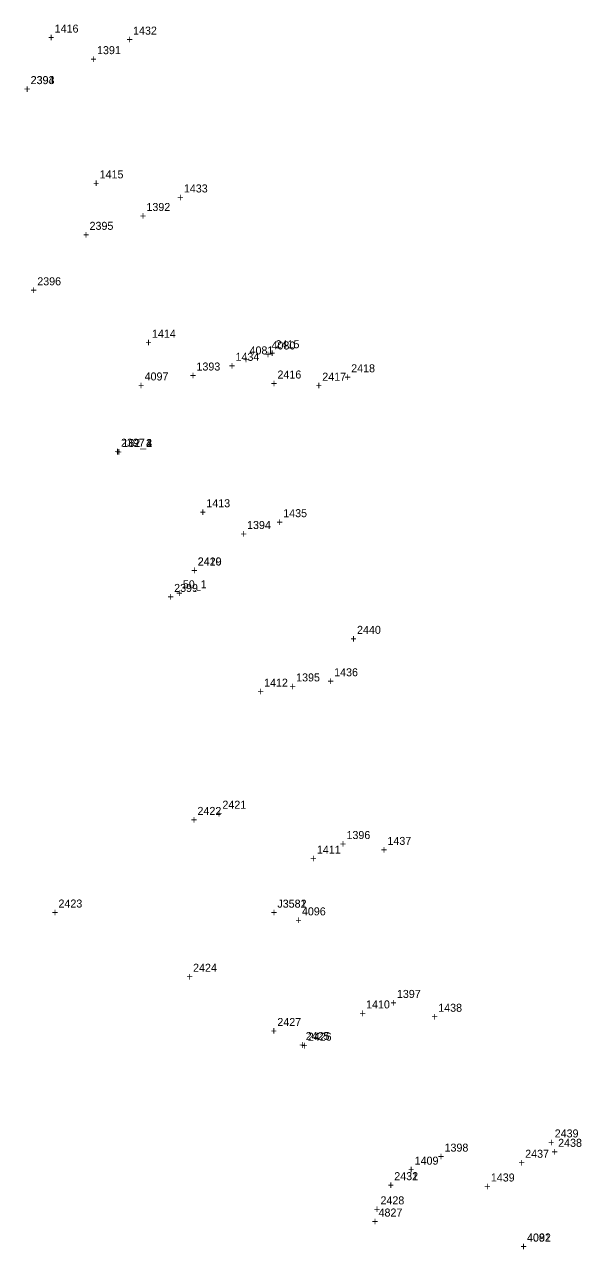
# Model space of a CAD drawing. Extents: x 1036751 to 1042192, y 772604 to 785439.
# Drawn here: x 1038206.7 to 1038380.7, y 779383.2 to 779766 of the extents above; entities that cross this region are included whole.
import ezdxf

# ---------------------------------------------------------------- set-up
doc = ezdxf.new("R2010")
doc.units = 0
for name, color, linetype in [('S_Control_Geodetic_ControlPoint', 7, 'Continuous'), ('S_Control_Temp_Traverse', 7, 'Continuous'), ('S_Drainage_CB', 7, 'Continuous'), ('S_Drainage_Sump', 7, 'Continuous'), ('S_Ground_Elevation', 7, 'Continuous'), ('S_Property_IronPipeFound', 7, 'Continuous'), ('S_Property_Mailbox', 7, 'Continuous'), ('S_Roadway_Centerline', 7, 'Continuous'), ('S_Roadway_Edge_Pavement', 7, 'Continuous'), ('S_Traffic_Sign_DoublePost', 7, 'Continuous'), ('S_Traffic_Sign_SinglePost', 7, 'Continuous'), ('S_Trees_Conifer_Pay', 7, 'Continuous'), ('S_Utilities_GuyWire3', 7, 'Continuous'), ('S_Utilities_Hydrant', 7, 'Continuous'), ('S_Utilities_Pole_Power', 7, 'Continuous'), ('S_Utilities_UG_Electrical_Line', 7, 'Continuous'), ('S_Utilities_UG_Water_Line', 7, 'Continuous')]:
    doc.layers.add(name, color=color, linetype=linetype)

msp = doc.modelspace()

# ---------------------------------------------------------------- texts
at = {"layer": 'S_Control_Geodetic_ControlPoint'}
for s, p in [('+', (1038254.14, 779587.08)), ('+', (1038254.14, 779587.08)), ('+', (1038254.14, 779587.08)), ('+', (1038254.14, 779587.08)), ('+', (1038254.14, 779587.08)), ('+', (1038254.14, 779587.08)), ('+', (1038254.14, 779587.08)), ('+', (1038254.14, 779587.08)), ('+', (1038254.14, 779587.08)), ('+', (1038254.14, 779587.08)), ('+', (1038254.14, 779587.08)), ('+', (1038254.14, 779587.08)), ('+', (1038254.14, 779587.08)), ('+', (1038254.14, 779587.08)), ('50', (1038256.2, 779589.83)), ('50', (1038256.2, 779589.83)), ('50', (1038256.2, 779589.83)), ('50', (1038256.2, 779589.83)), ('50', (1038256.2, 779589.83)), ('50', (1038256.2, 779589.83)), ('50', (1038256.2, 779589.83)), ('50', (1038256.2, 779589.83)), ('50', (1038256.2, 779589.83)), ('50', (1038256.2, 779589.83)), ('50', (1038256.2, 779589.83)), ('50', (1038256.2, 779589.83)), ('50', (1038256.2, 779589.83)), ('50_1', (1038256.2, 779589.83))]:
    msp.add_text(s, height=2.5, dxfattribs=at).set_placement(p)
at = {"layer": 'S_Control_Temp_Traverse'}
for s, p in [('162', (1038237.3, 779633.97)), ('162', (1038237.3, 779633.97)), ('162_1', (1038237.3, 779633.97)), ('162_3', (1038237.3, 779633.97)), ('162_2', (1038237.3, 779633.97)), ('162_4', (1038237.3, 779633.97)), ('+', (1038235.24, 779631.22)), ('+', (1038235.24, 779631.22)), ('+', (1038235.24, 779631.22)), ('+', (1038235.24, 779631.22)), ('+', (1038235.24, 779631.22)), ('+', (1038235.24, 779631.22))]:
    msp.add_text(s, height=2.5, dxfattribs=at).set_placement(p)
at = {"layer": 'S_Drainage_CB'}
for s, p in [('2393', (1038208.69, 779747.37)), ('+', (1038206.63, 779744.62)), ('2419', (1038260.85, 779596.98)), ('+', (1038258.79, 779594.23)), ('J3581', (1038285.73, 779490.02)), ('+', (1038283.67, 779487.27)), ('2431', (1038322.25, 779404.89)), ('+', (1038320.19, 779402.14))]:
    msp.add_text(s, height=2.5, dxfattribs=at).set_placement(p)
at = {"layer": 'S_Drainage_Sump'}
for s, p in [('2394', (1038208.64, 779747.36)), ('+', (1038206.58, 779744.61)), ('2420', (1038260.87, 779596.94)), ('+', (1038258.81, 779594.19)), ('J3582', (1038285.74, 779490.05)), ('+', (1038283.68, 779487.3)), ('2432', (1038322.25, 779404.89)), ('+', (1038320.18, 779402.14))]:
    msp.add_text(s, height=2.5, dxfattribs=at).set_placement(p)
at = {"layer": 'S_Ground_Elevation'}
for s, p in [('4827', (1038317.34, 779393.52)), ('+', (1038315.28, 779390.77))]:
    msp.add_text(s, height=2.5, dxfattribs=at).set_placement(p)
at = {"layer": 'S_Property_IronPipeFound'}
for s, p in [('2399', (1038253.49, 779588.69)), ('+', (1038251.43, 779585.94))]:
    msp.add_text(s, height=2.5, dxfattribs=at).set_placement(p)
at = {"layer": 'S_Property_Mailbox'}
for s, p in [('2395', (1038227.07, 779701.83)), ('+', (1038225.01, 779699.08)), ('2440', (1038310.61, 779575.59)), ('+', (1038308.55, 779572.84))]:
    msp.add_text(s, height=2.5, dxfattribs=at).set_placement(p)
at = {"layer": 'S_Roadway_Centerline'}
for s, p in [('1391', (1038229.4, 779756.72)), ('+', (1038227.34, 779753.97)), ('1392', (1038244.83, 779707.72)), ('+', (1038242.77, 779704.97)), ('1393', (1038260.46, 779657.87)), ('+', (1038258.39, 779655.12)), ('1394', (1038276.26, 779608.35)), ('+', (1038274.2, 779605.6)), ('1395', (1038291.59, 779560.73)), ('+', (1038289.53, 779557.98)), ('1396', (1038307.32, 779511.48)), ('+', (1038305.26, 779508.73)), ('1397', (1038323.07, 779461.83)), ('+', (1038321.01, 779459.08)), ('+', (1038335.89, 779411.06)), ('1398', (1038337.95, 779413.81))]:
    msp.add_text(s, height=2.5, dxfattribs=at).set_placement(p)
at = {"layer": 'S_Roadway_Edge_Pavement'}
for s, p in [('1416', (1038216.17, 779763.45)), ('1432', (1038240.65, 779762.82)), ('+', (1038214.11, 779760.7)), ('+', (1038238.59, 779760.07)), ('1415', (1038230.21, 779717.91)), ('+', (1038228.15, 779715.16)), ('1433', (1038256.53, 779713.51)), ('+', (1038254.46, 779710.76)), ('1414', (1038246.56, 779668.12)), ('+', (1038244.5, 779665.37)), ('1434', (1038272.66, 779660.9)), ('+', (1038270.6, 779658.15)), ('1413', (1038263.54, 779615.15)), ('+', (1038261.48, 779612.4)), ('1435', (1038287.56, 779612.05)), ('+', (1038285.5, 779609.3)), ('1436', (1038303.47, 779562.34)), ('+', (1038279.52, 779556.33)), ('1412', (1038281.58, 779559.08)), ('+', (1038301.41, 779559.59)), ('1411', (1038298.08, 779506.91)), ('+', (1038318.04, 779506.89)), ('1437', (1038320.11, 779509.64)), ('+', (1038296.01, 779504.16)), ('1410', (1038313.44, 779458.56)), ('1438', (1038335.98, 779457.51)), ('+', (1038311.38, 779455.81)), ('+', (1038333.92, 779454.76)), ('+', (1038326.55, 779406.98)), ('1409', (1038328.61, 779409.73)), ('1439', (1038352.41, 779404.48)), ('+', (1038350.35, 779401.73))]:
    msp.add_text(s, height=2.5, dxfattribs=at).set_placement(p)
at = {"layer": 'S_Traffic_Sign_DoublePost'}
for s, p in [('2418', (1038308.79, 779657.32)), ('+', (1038297.7, 779651.94)), ('2417', (1038299.76, 779654.69)), ('+', (1038306.73, 779654.57)), ('2422', (1038260.78, 779519.01)), ('+', (1038266.5, 779518.2)), ('2421', (1038268.56, 779520.95)), ('+', (1038258.72, 779516.26))]:
    msp.add_text(s, height=2.5, dxfattribs=at).set_placement(p)
at = {"layer": 'S_Traffic_Sign_SinglePost'}
for s, p in [('2428', (1038317.94, 779397.33)), ('+', (1038315.88, 779394.58))]:
    msp.add_text(s, height=2.5, dxfattribs=at).set_placement(p)
at = {"layer": 'S_Trees_Conifer_Pay'}
for s, p in [('2396', (1038210.73, 779684.5)), ('+', (1038208.66, 779681.75)), ('2397', (1038236.89, 779634.06)), ('+', (1038234.83, 779631.31))]:
    msp.add_text(s, height=2.5, dxfattribs=at).set_placement(p)
at = {"layer": 'S_Utilities_GuyWire3'}
for s, p in [('2427', (1038285.72, 779453.06)), ('+', (1038283.66, 779450.31)), ('2439', (1038372.36, 779418.24)), ('+', (1038370.3, 779415.49)), ('2438', (1038373.44, 779415.31)), ('+', (1038371.38, 779412.56))]:
    msp.add_text(s, height=2.5, dxfattribs=at).set_placement(p)
at = {"layer": 'S_Utilities_Hydrant'}
for s, p in [('2415', (1038285.18, 779664.83)), ('+', (1038283.12, 779662.08))]:
    msp.add_text(s, height=2.5, dxfattribs=at).set_placement(p)
at = {"layer": 'S_Utilities_Pole_Power'}
for s, p in [('2416', (1038285.77, 779655.37)), ('+', (1038283.71, 779652.62)), ('+', (1038293.17, 779445.71)), ('2426', (1038295.23, 779448.46)), ('2437', (1038363.14, 779411.89)), ('+', (1038361.08, 779409.14))]:
    msp.add_text(s, height=2.5, dxfattribs=at).set_placement(p)
at = {"layer": 'S_Utilities_UG_Electrical_Line'}
for s, p in [('+', (1038215.3, 779487.33)), ('2423', (1038217.36, 779490.08)), ('2424', (1038259.4, 779470.01)), ('+', (1038257.33, 779467.26)), ('2425', (1038294.59, 779448.67)), ('+', (1038292.53, 779445.92))]:
    msp.add_text(s, height=2.5, dxfattribs=at).set_placement(p)
at = {"layer": 'S_Utilities_UG_Water_Line'}
for s, p in [('4080', (1038283.89, 779664.45)), ('+', (1038274.97, 779660.15)), ('4081', (1038277.04, 779662.9)), ('+', (1038281.83, 779661.7)), ('+', (1038242.19, 779652.02)), ('4097', (1038244.26, 779654.77)), ('4096', (1038293.4, 779487.63)), ('+', (1038291.34, 779484.88)), ('4091', (1038363.7, 779385.66)), ('4082', (1038363.72, 779385.74)), ('+', (1038361.64, 779382.91)), ('+', (1038361.66, 779382.99))]:
    msp.add_text(s, height=2.5, dxfattribs=at).set_placement(p)

doc.saveas('drawing.dxf')
